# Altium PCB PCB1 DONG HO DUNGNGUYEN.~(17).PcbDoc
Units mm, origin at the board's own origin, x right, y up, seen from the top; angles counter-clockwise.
Board outline 54.94 x 47.62 mm, 2 copper layers (Top Layer, Bottom Layer); 32 components, 16 nets, 156 pads, 0 vias.
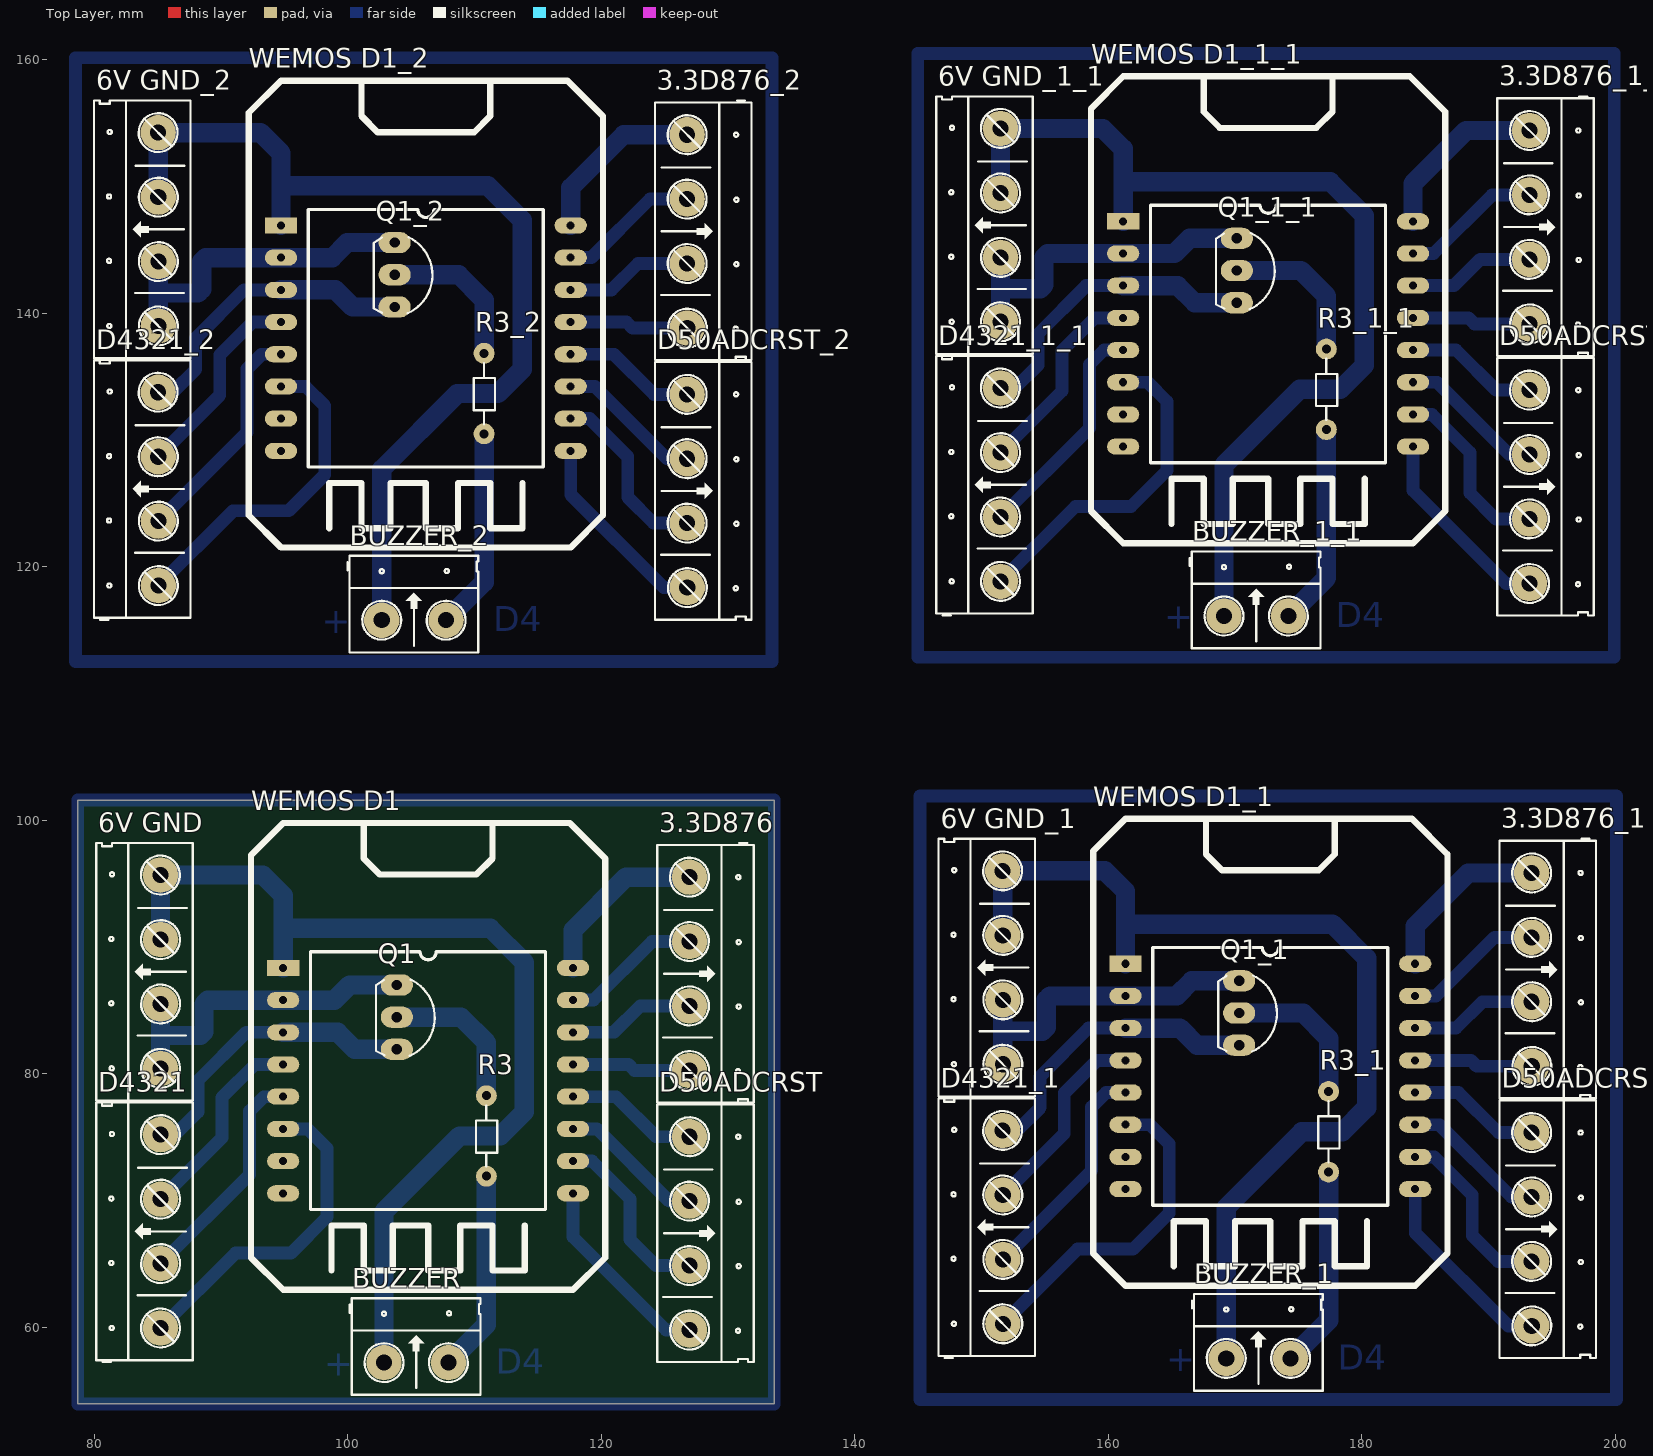
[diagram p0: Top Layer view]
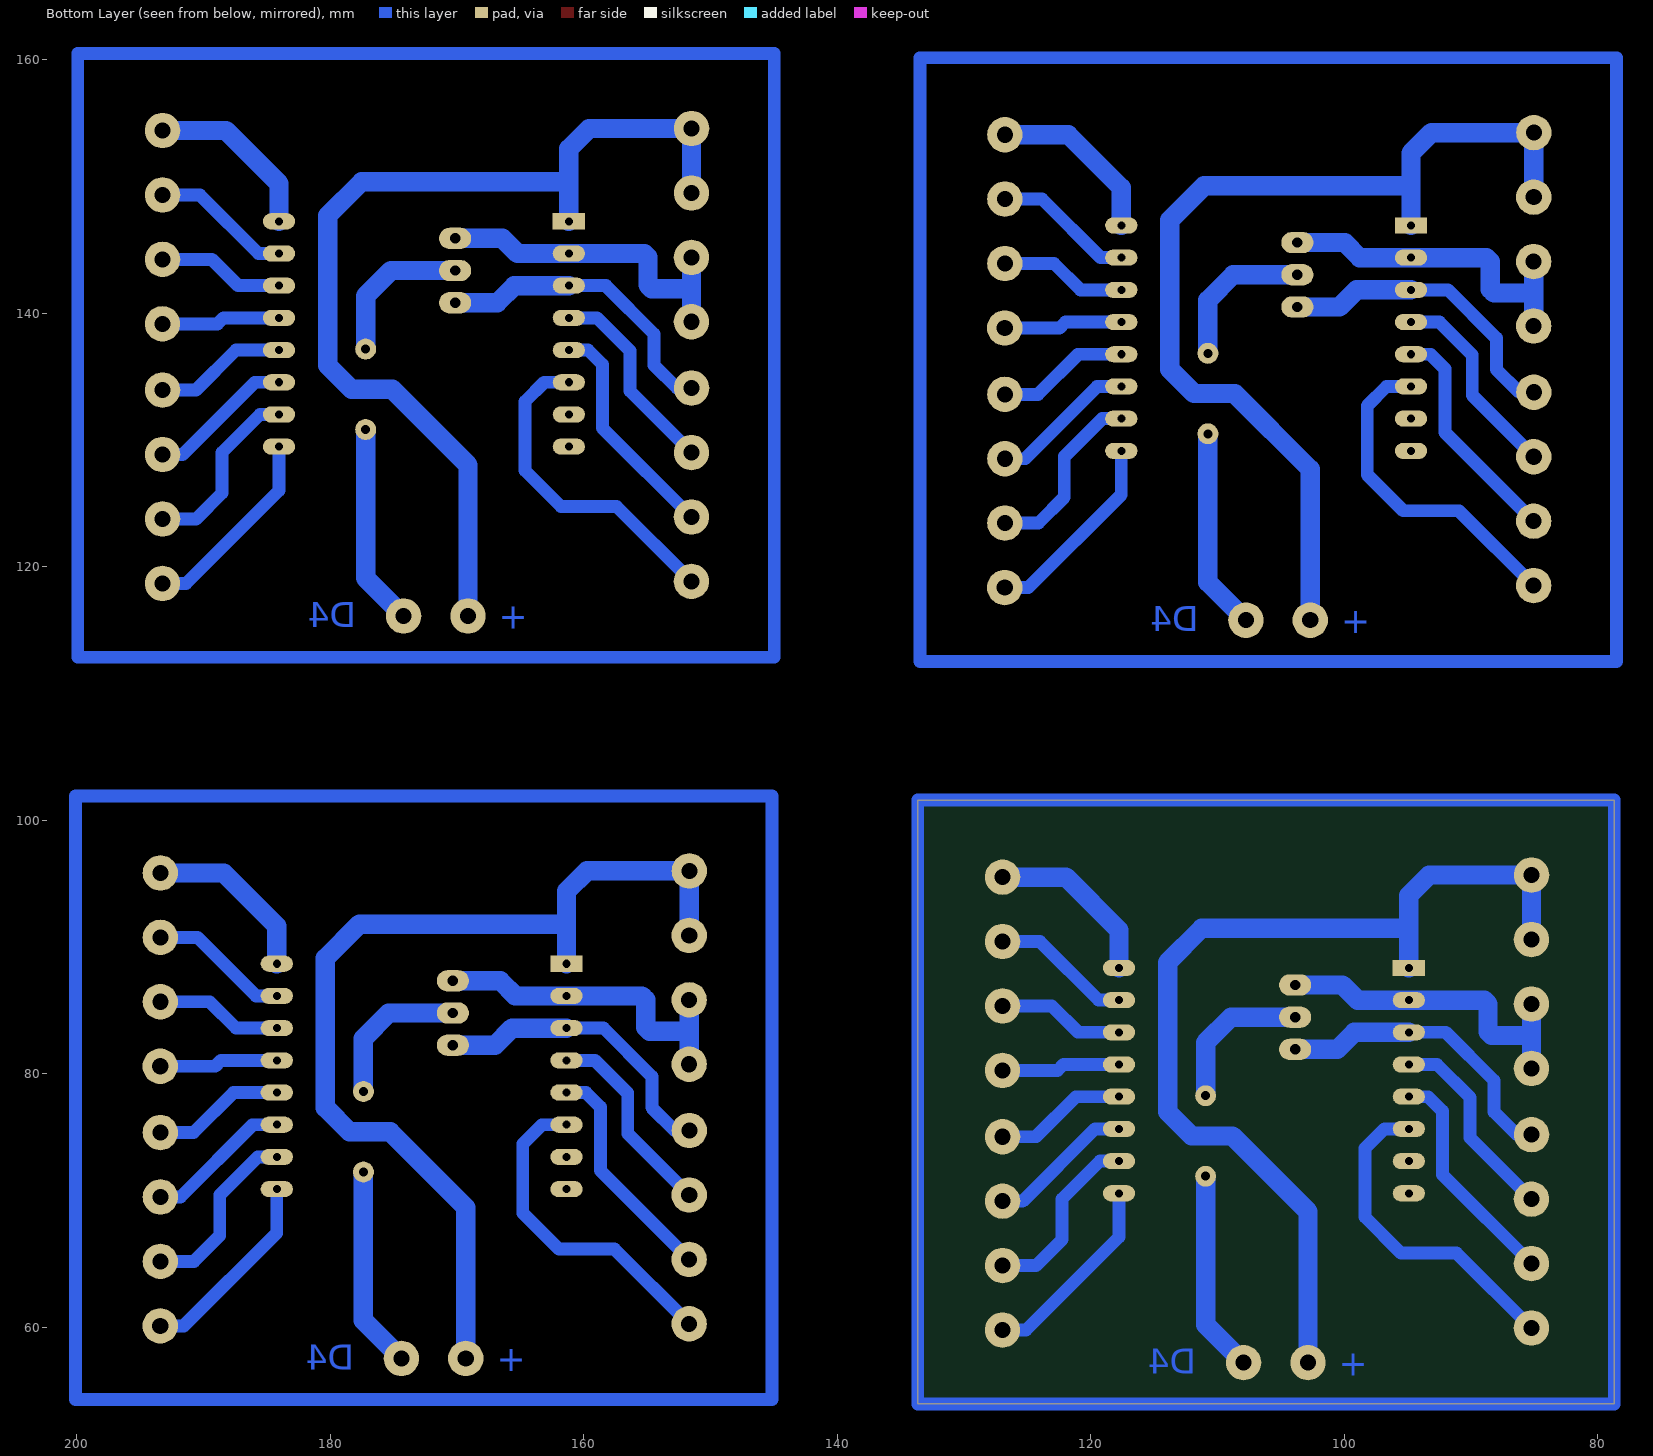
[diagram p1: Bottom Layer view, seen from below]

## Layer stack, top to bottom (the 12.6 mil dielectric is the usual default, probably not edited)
Top Solder: solder mask 0.0102, Solder Resist, Dk 3.5
Top Layer: signal copper 0.0356
Dielectric 1: dielectric 0.32, FR-4, Dk 4.8
Bottom Layer: signal copper 0.0356
Bottom Solder: solder mask 0.0102, Solder Resist, Dk 3.5

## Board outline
78.689,53.975 78.689,101.6 133.629,101.6 133.629,53.975

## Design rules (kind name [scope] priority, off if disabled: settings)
Clearance [All] p1: gap=0.254 ignorepadtopadclearanceinfootprint=FALSE except(0: Arc-Hole Track-Hole SMDPad-Hole THPad-Hole Via-Hole Fill-Hole Poly-Hole Region-Hole Text-Hole)
PolygonConnect [All] p1: connectstyle=Relief reliefconductorwidth=0.254 reliefentries=4 polygonreliefangle="90 Angle" airgapwidth=0.254
RoutingVias [All] p1: holewidth=0.711 width=1.27 viastyle="Through Hole" minholewidth=0.711 minwidth=1.27 maxholewidth=2.54 maxwidth=2.54
SolderMaskExpansion [All] p1: expansion=0.102
Width [All] p1: maxlimit=2.032 minlimit=1.016 preferedwidth=1.524
30 further rules are at their usual default settings.

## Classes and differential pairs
component class DONG_HO: 3.3D876 "6V GND" BUZZER D50ADCRST D4321 HD? Q1 R3 "WEMOS D1"

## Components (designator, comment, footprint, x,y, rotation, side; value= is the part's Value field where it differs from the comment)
3.3D876 "Header 4" HED4 126.939,95.528 r270 top
3.3D876_1 "Header 4" HED4 193.386,95.858 r270 top (schematic designator 3.3D876)
3.3D876_1_1 "Header 4" HED4 193.208,154.43 r270 top (schematic designator 3.3D876)
3.3D876_2 "Header 4" HED4 126.761,154.1 r270 top (schematic designator 3.3D876)
"6V GND" "Header 4" HED4 85.219,80.44 r90 top
"6V GND_1" "Header 4" HED4 151.665,80.77 r90 top (schematic designator "6V GND")
"6V GND_1_1" "Header 4" HED4 151.487,139.343 r90 top (schematic designator "6V GND")
"6V GND_2" "Header 4" HED4 85.041,139.013 r90 top (schematic designator "6V GND")
BUZZER "Header 2" HED2 102.845,57.226 r0 top
BUZZER_1 "Header 2" HED2 169.291,57.556 r0 top (schematic designator BUZZER)
BUZZER_1_1 "Header 2" HED2 169.113,116.129 r0 top (schematic designator BUZZER)
BUZZER_2 "Header 2" HED2 102.667,115.799 r0 top (schematic designator BUZZER)
D50ADCRST "Header 4" HED4 126.939,75.047 r270 top
D50ADCRST_1 "Header 4" HED4 193.386,75.377 r270 top (schematic designator D50ADCRST)
D50ADCRST_1_1 "Header 4" HED4 193.208,133.95 r270 top (schematic designator D50ADCRST)
D50ADCRST_2 "Header 4" HED4 126.761,133.619 r270 top (schematic designator D50ADCRST)
D4321 "Header 4" HED4 85.219,59.959 r90 top
D4321_1 "Header 4" HED4 151.665,60.29 r90 top (schematic designator D4321)
D4321_1_1 "Header 4" HED4 151.487,118.862 r90 top (schematic designator D4321)
D4321_2 "Header 4" HED4 85.041,118.532 r90 top (schematic designator D4321)
Q1 "C1815" QTO-92 103.861,84.48 r270 top
Q1_1 "C1815" QTO-92 170.307,84.811 r270 top (schematic designator Q1)
Q1_1_1 "C1815" QTO-92 170.129,143.383 r270 top (schematic designator Q1)
Q1_2 "C1815" QTO-92 103.683,143.053 r270 top (schematic designator Q1)
R3 "100" RES-1/8W-SMALL 110.922,75.108 r270 top
R3_1 "100" RES-1/8W-SMALL 177.368,75.438 r270 top (schematic designator R3)
R3_1_1 "100" RES-1/8W-SMALL 177.19,134.01 r270 top (schematic designator R3)
R3_2 "100" RES-1/8W-SMALL 110.744,133.68 r270 top (schematic designator R3)
"WEMOS D1" "Component_1" "ESP WEMOS MINI" 94.894,88.367 r0 top
"WEMOS D1_1" "Component_1" "ESP WEMOS MINI" 161.341,88.697 r0 top (schematic designator "WEMOS D1")
"WEMOS D1_1_1" "Component_1" "ESP WEMOS MINI" 161.163,147.269 r0 top (schematic designator "WEMOS D1")
"WEMOS D1_2" "Component_1" "ESP WEMOS MINI" 94.717,146.939 r0 top (schematic designator "WEMOS D1")

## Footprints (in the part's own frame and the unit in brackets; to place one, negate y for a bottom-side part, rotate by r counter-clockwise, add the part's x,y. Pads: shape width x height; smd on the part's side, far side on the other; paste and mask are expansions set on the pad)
"ESP WEMOS MINI" [mm]
  rect 2.54x1.27 hole 0.635: 1(0,0)
  oval 2.54x1.27 hole 0.635: 2(0,-2.54) 3(0,-5.08) 4(0,-7.62) 5(0,-10.16) 6(0,-12.7) 7(0,-15.24) 8(0,-17.78) 9(22.86,-17.78) 10(22.86,-15.24) 11(22.86,-12.7) 12(22.86,-10.16) 13(22.86,-7.62) 14(22.86,-5.08) 15(22.86,-2.54) 16(22.86,0)
  silkscreen extent -2.54,-25.4 25.4,11.43
HED2 [mil] "Header 2, 2 pin, hight 300mil, Pin to Pin 200, Colour Green"
  round 110 hole 50: 1(0,0) 2(200,0)
  silkscreen extent -106,-100 300,200, body extent -92,-140 302,155, height 394
HED4 [mil] "Header 4, 4 pin, hight 300mil, Pin to Pin 200, Colour Green"
  round 110 hole 50: 1(0,0) 2(200,0) 3(400.06,0.06) 4(600.39,0.39)
  silkscreen extent -106,-100 700,200
QTO-92 [mil] "TO-92"
  oval 66x100 hole 32: 1(-100,0) 2(0,0) 3(100,0)
  silkscreen extent -117,-65 120,118, body extent -109,-66 109,95, height 245
RES-1/8W-SMALL [mil] "R 1/8W, 2 pin, 200mil"
  round 65 hole 28: 1(-125,0) 2(125,0)
  silkscreen extent -95,-32 95,34, body extent -135,-35 135,37, height 76

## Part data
3.3D876 3.3D876_1 3.3D876_1_1 3.3D876_2 "6V GND" "6V GND_1" "6V GND_1_1" "6V GND_2" D50ADCRST D50ADCRST_1 D50ADCRST_1_1 D50ADCRST_2 D4321 D4321_1 D4321_1_1 D4321_2: library part Hed4, "Header 4 (Green)"
BUZZER BUZZER_1 BUZZER_1_1 BUZZER_2: library part Hed2, "Header 2 (Green)"
Q1 Q1_1 Q1_1_1 Q1_2: "NPN 600mW, ECB"
R3 R3_1 R3_1_1 R3_2: library part Res, "Res", Manufacturer="Generic Components"

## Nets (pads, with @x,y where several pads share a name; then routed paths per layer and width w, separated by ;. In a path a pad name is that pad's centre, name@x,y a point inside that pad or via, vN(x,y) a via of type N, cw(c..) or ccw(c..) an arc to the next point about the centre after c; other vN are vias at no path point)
D4: "WEMOS D1.3" D4321.4 Q1.3 | length 24
  Bottom Layer w1.016: D4321.4 86.36,75.209 88.163,77.013 88.163,79.477 91.973,83.287 94.894,83.287
  Bottom Layer w1.524: 94.894,83.287 99.187,83.287 100.533,81.94 Q1.3
GND: "6V GND.1" "6V GND.2" "WEMOS D1.2" Q1.1 | length 26.7
  Bottom Layer w1.524: 85.219,80.44 85.219,83.033 ; 85.219,85.52 85.219,83.033 ; Q1.1 100.127,87.02 98.933,85.827 94.894,85.827 88.951,85.827 88.644,85.52 88.644,83.336 88.341,83.033 85.219,83.033
Net3.3D876_1: 3.3D876.1 "WEMOS D1.16" | length 13.9
  Bottom Layer w1.524: 117.754,88.367 117.754,91.338 121.944,95.528 3.3D876.1
Net3.3D876_2: 3.3D876.2 "WEMOS D1.15" | length 11.1
  Bottom Layer w1.016: 117.754,85.827 119.38,85.827 124.001,90.448 3.3D876.2
Net3.3D876_3: 3.3D876.3 "WEMOS D1.14" | length 10
  Bottom Layer w1.016: 117.754,83.287 120.98,83.287 123.06,85.366 3.3D876.3
Net3.3D876_4: 3.3D876.4 "WEMOS D1.13" | length 9.4
  Bottom Layer w1.016: 117.754,80.747 122.149,80.747 122.617,80.278 3.3D876.4
NetBUZZER_2: BUZZER.2 R3.2 | length 15.9
  Bottom Layer w1.524: BUZZER.2 110.922,60.223 R3.2
NetD50ADCRST_1: "WEMOS D1.12" D50ADCRST.1 | length 10.5
  Bottom Layer w1.016: 117.754,78.207 121.158,78.207 124.318,75.047 D50ADCRST.1
NetD50ADCRST_2: "WEMOS D1.11" D50ADCRST.2 | length 11.5
  Bottom Layer w1.016: 117.754,75.667 119.659,75.667 125.359,69.967 D50ADCRST.2
NetD50ADCRST_3: "WEMOS D1.10" D50ADCRST.3 | length 14.5
  Bottom Layer w1.016: 117.754,73.127 119.253,73.127 122.25,70.129 122.25,66.929 124.294,64.885 D50ADCRST.3
NetD50ADCRST_4: "WEMOS D1.9" D50ADCRST.4 | length 15.7
  Bottom Layer w1.016: 117.754,70.587 117.754,67.132 125.09,59.797 D50ADCRST.4
NetD4321_1: "WEMOS D1.6" D4321.1 | length 26.3
  Bottom Layer w1.016: D4321.1 91.121,65.862 95.504,65.862 98.349,68.707 98.349,74.143 96.825,75.667 94.894,75.667
NetD4321_2: "WEMOS D1.5" D4321.2 | length 18.1
  Bottom Layer w1.016: D4321.2 92.227,72.048 92.227,77.064 93.37,78.207 94.894,78.207
NetD4321_3: "WEMOS D1.4" D4321.3 | length 15.9
  Bottom Layer w1.016: D4321.3 90.068,74.972 90.068,78.156 92.659,80.747 94.894,80.747
NetQ1_2: Q1.2 R3.1 | length 12.1
  Bottom Layer w1.524: Q1.2 108.915,84.48 110.922,82.474 R3.1
VCC: "6V GND.3" "6V GND.4" "WEMOS D1.1" BUZZER.1 | length 79.3
  Bottom Layer w1.524: 85.217,90.602 85.217,95.682 85.209,95.69 93.286,95.69 94.894,94.082 94.894,91.491 ; 94.894,88.367 94.894,91.491 ; BUZZER.1 102.845,69.139 108.814,75.108 112.014,75.108 113.919,77.013 113.919,88.798 111.227,91.491 94.894,91.491
pads on no net: 3.3D876_1.1 3.3D876_1.2 3.3D876_1.3 3.3D876_1.4 3.3D876_1_1.1 3.3D876_1_1.2 3.3D876_1_1.3 3.3D876_1_1.4 3.3D876_2.1 3.3D876_2.2 3.3D876_2.3 3.3D876_2.4 "6V GND_1.1" "6V GND_1.2" "6V GND_1.3" "6V GND_1.4" "6V GND_1_1.1" "6V GND_1_1.2" "6V GND_1_1.3" "6V GND_1_1.4" "6V GND_2.1" "6V GND_2.2" "6V GND_2.3" "6V GND_2.4" "WEMOS D1.7" "WEMOS D1.8" "WEMOS D1_1.1" "WEMOS D1_1.2" "WEMOS D1_1.3" "WEMOS D1_1.4" "WEMOS D1_1.5" "WEMOS D1_1.6" "WEMOS D1_1.7" "WEMOS D1_1.8" "WEMOS D1_1.9" "WEMOS D1_1.10" "WEMOS D1_1.11" "WEMOS D1_1.12" "WEMOS D1_1.13" "WEMOS D1_1.14" "WEMOS D1_1.15" "WEMOS D1_1.16" "WEMOS D1_1_1.1" "WEMOS D1_1_1.2" "WEMOS D1_1_1.3" "WEMOS D1_1_1.4" "WEMOS D1_1_1.5" "WEMOS D1_1_1.6" "WEMOS D1_1_1.7" "WEMOS D1_1_1.8" "WEMOS D1_1_1.9" "WEMOS D1_1_1.10" "WEMOS D1_1_1.11" "WEMOS D1_1_1.12" "WEMOS D1_1_1.13" "WEMOS D1_1_1.14" "WEMOS D1_1_1.15" "WEMOS D1_1_1.16" "WEMOS D1_2.1" "WEMOS D1_2.2" "WEMOS D1_2.3" "WEMOS D1_2.4" "WEMOS D1_2.5" "WEMOS D1_2.6" "WEMOS D1_2.7" "WEMOS D1_2.8" "WEMOS D1_2.9" "WEMOS D1_2.10" "WEMOS D1_2.11" "WEMOS D1_2.12" "WEMOS D1_2.13" "WEMOS D1_2.14" "WEMOS D1_2.15" "WEMOS D1_2.16" BUZZER_1.1 BUZZER_1.2 BUZZER_1_1.1 BUZZER_1_1.2 BUZZER_2.1 BUZZER_2.2 D50ADCRST_1.1 D50ADCRST_1.2 D50ADCRST_1.3 D50ADCRST_1.4 D50ADCRST_1_1.1 D50ADCRST_1_1.2 D50ADCRST_1_1.3 D50ADCRST_1_1.4 D50ADCRST_2.1 D50ADCRST_2.2 D50ADCRST_2.3 D50ADCRST_2.4 D4321_1.1 D4321_1.2 D4321_1.3 D4321_1.4 D4321_1_1.1 D4321_1_1.2 D4321_1_1.3 D4321_1_1.4 D4321_2.1 D4321_2.2 D4321_2.3 D4321_2.4 Q1_1.1 Q1_1.2 Q1_1.3 Q1_1_1.1 Q1_1_1.2 Q1_1_1.3 Q1_2.1 Q1_2.2 Q1_2.3 R3_1.1 R3_1.2 R3_1_1.1 R3_1_1.2 R3_2.1 R3_2.2
copper on no net: | length 1765.3
  Bottom Layer w1.016: 85.031,133.782 86.182,133.782 87.986,135.585 87.986,138.049 91.796,141.859 94.717,141.859 ; 85.039,128.693 89.891,133.545 89.891,136.728 92.481,139.319 94.717,139.319 ; 85.041,118.532 90.944,124.435 95.326,124.435 98.171,127.279 98.171,132.715 96.647,134.239 94.717,134.239 ; 85.041,123.612 92.05,130.621 92.05,135.636 93.193,136.779 94.717,136.779 ; 117.577,129.159 117.577,125.705 124.912,118.369 126.771,118.369 ; 117.577,131.699 119.075,131.699 122.072,128.702 122.072,125.501 124.116,123.458 126.763,123.458 ; 117.577,134.239 119.482,134.239 125.181,128.539 126.761,128.539 ; 117.577,136.779 120.98,136.779 124.14,133.619 126.761,133.619 ; 117.577,139.319 121.971,139.319 122.44,138.85 126.771,138.85 ; 117.577,141.859 120.802,141.859 122.882,143.939 126.763,143.939 ; 117.577,144.399 119.202,144.399 123.823,149.02 126.761,149.02 ; 151.477,134.112 152.629,134.112 154.432,135.915 154.432,138.379 158.242,142.189 161.163,142.189 ; 151.486,129.024 156.337,133.875 156.337,137.058 158.928,139.649 161.163,139.649 ; 151.487,118.862 157.39,124.765 161.773,124.765 164.617,127.61 164.617,133.045 163.093,134.569 161.163,134.569 ; 151.487,123.942 158.496,130.951 158.496,135.966 159.639,137.109 161.163,137.109 ; 151.655,75.54 152.806,75.54 154.61,77.343 154.61,79.807 158.42,83.617 161.341,83.617 ; 151.663,70.451 156.515,75.303 156.515,78.486 159.106,81.077 161.341,81.077 ; 151.665,60.29 157.568,66.192 161.95,66.192 164.795,69.037 164.795,74.473 163.271,75.997 161.341,75.997 ; 151.665,65.37 158.674,72.378 158.674,77.394 159.817,78.537 161.341,78.537 ; 184.023,129.489 184.023,126.035 191.358,118.7 193.218,118.7 ; 184.023,132.029 185.522,132.029 188.519,129.032 188.519,125.832 190.562,123.788 193.209,123.788 ; 184.023,134.569 185.928,134.569 191.628,128.87 193.208,128.87 ; 184.023,137.109 187.427,137.109 190.586,133.95 193.208,133.95 ; 184.023,139.649 188.417,139.649 188.886,139.18 193.218,139.18 ; 184.023,142.189 187.249,142.189 189.328,144.269 193.209,144.269 ; 184.023,144.729 185.649,144.729 190.27,149.35 193.208,149.35 ; 184.201,70.917 184.201,67.462 191.536,60.127 193.396,60.127 ; 184.201,73.457 185.699,73.457 188.697,70.46 188.697,67.259 190.74,65.216 193.387,65.216 ; 184.201,75.997 186.106,75.997 191.805,70.297 193.386,70.297 ; 184.201,78.537 187.604,78.537 190.764,75.377 193.386,75.377 ; 184.201,81.077 188.595,81.077 189.064,80.608 193.396,80.608 ; 184.201,83.617 187.427,83.617 189.506,85.696 193.387,85.696 ; 184.201,86.157 185.826,86.157 190.448,90.778 193.386,90.778 ; 78.511,112.547 133.452,112.547 133.452,160.172 78.511,160.172 78.511,112.547 ; 78.689,53.975 78.689,101.6 133.629,101.6 133.629,53.975 78.689,53.975 ; 144.958,112.878 144.958,160.503 199.898,160.503 199.898,112.878 144.958,112.878 ; 145.136,54.305 200.076,54.305 200.076,101.93 145.136,101.93 145.136,54.305
  Bottom Layer w1.524: 85.039,149.174 85.039,154.254 85.031,154.263 93.108,154.263 94.717,152.654 94.717,150.063 ; 85.041,139.013 85.041,141.605 ; 85.041,144.093 85.041,141.605 ; 94.717,141.859 99.009,141.859 100.355,140.513 103.683,140.513 ; 94.717,146.939 94.717,150.063 ; 102.667,115.799 102.667,127.711 108.636,133.68 111.836,133.68 113.741,135.585 113.741,147.371 111.049,150.063 94.717,150.063 ; 103.683,143.053 108.737,143.053 110.744,141.046 110.744,136.855 ; 103.683,145.593 99.949,145.593 98.755,144.399 94.717,144.399 88.773,144.399 88.467,144.093 88.467,141.908 88.163,141.605 85.041,141.605 ; 107.747,115.799 110.744,118.796 110.744,130.505 ; 117.577,146.939 117.577,149.911 121.766,154.1 126.761,154.1 ; 151.486,149.504 151.486,154.584 151.477,154.593 159.554,154.593 161.163,152.984 161.163,150.393 ; 151.487,139.343 151.487,141.935 ; 151.487,144.423 151.487,141.935 ; 151.663,90.932 151.663,96.012 151.655,96.02 159.732,96.02 161.341,94.412 161.341,91.821 ; 151.665,80.77 151.665,83.363 ; 151.665,85.85 151.665,83.363 ; 161.163,142.189 165.456,142.189 166.802,140.843 170.129,140.843 ; 161.163,147.269 161.163,150.393 ; 161.341,83.617 165.633,83.617 166.98,82.271 170.307,82.271 ; 161.341,88.697 161.341,91.821 ; 169.113,116.129 169.113,128.041 175.082,134.01 178.283,134.01 180.188,135.915 180.188,147.701 177.495,150.393 161.163,150.393 ; 169.291,57.556 169.291,69.469 175.26,75.438 178.46,75.438 180.365,77.343 180.365,89.129 177.673,91.821 161.341,91.821 ; 170.129,143.383 175.184,143.383 177.19,141.376 177.19,137.185 ; 170.129,145.923 166.395,145.923 165.202,144.729 161.163,144.729 155.219,144.729 154.913,144.423 154.913,142.238 154.61,141.935 151.487,141.935 ; 170.307,84.811 175.362,84.811 177.368,82.804 177.368,78.613 ; 170.307,87.351 166.573,87.351 165.379,86.157 161.341,86.157 155.397,86.157 155.091,85.85 155.091,83.666 154.788,83.363 151.665,83.363 ; 174.193,116.129 177.19,119.126 177.19,130.835 ; 174.371,57.556 177.368,60.554 177.368,72.263 ; 184.023,147.269 184.023,150.241 188.212,154.43 193.208,154.43 ; 184.201,88.697 184.201,91.669 188.39,95.858 193.386,95.858

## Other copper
Bottom Layer:
  text "D4" at 177.927,115.24 h2
  text "+" at 164.389,115.113 h2
  text "D4" at 111.481,114.91 h2
  text "+" at 97.942,114.783 h2
  text "D4" at 178.105,56.667 h2
  text "+" at 164.567,56.54 h2
  text "D4" at 111.658,56.337 h2
  text "+" at 98.12,56.21 h2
